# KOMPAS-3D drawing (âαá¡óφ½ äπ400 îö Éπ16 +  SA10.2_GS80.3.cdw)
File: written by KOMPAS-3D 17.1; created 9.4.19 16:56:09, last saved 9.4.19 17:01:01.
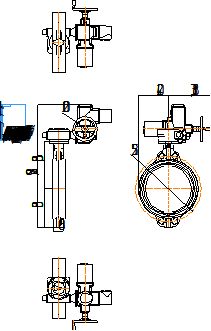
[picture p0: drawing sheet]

Sheet 1: A4, portrait

Title block, sheet 1: name: Гранвэл Ду400 МФ Ру16 + / SA10.2/GS80.3; material: Внимание! Данный продукт является объектом авторского права ООО «Торговый Дом АДЛ». / Запрещается изменение, копирование, распространение / (в том числе путем копирования на другие сайты и ресурсы в Интернете) / или любое иное использование информации и объектов без предварительного / согласия правообладателя (ООО «Торговый Дом АДЛ»).; mass: 168,46; sheets: 1; organisation: ООО "Торговый дом АДЛ"; sheet format: A4; stored path: \\adlc.lan\data\АДЛ_ПКД\3D-модели\ADL production\Дисковые поворотные затворы ГРАНВЭЛ\межфланцевый с эл.приводом Auma Ру 16\KOMPAS 2D\Гранвэл Ду400 МФ Ру16 +  SA10.2_GS80.3.cdw

Views: Вид 1, Проекционный вид 2, Проекционный вид 3, Проекционный вид 4
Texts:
  user
Dimensions and other numbers on the sheet: 380,3; 308; 80; 982,8; 200; 240; 333,78; 525; 1:1; 1; 168,46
